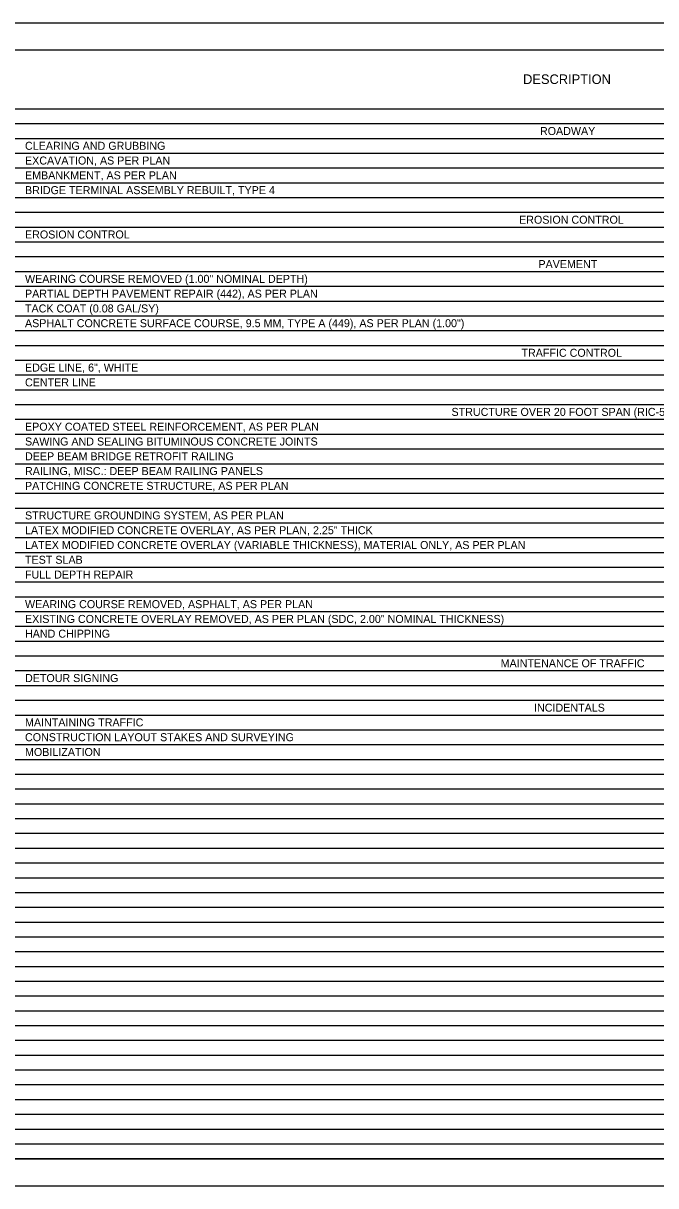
# Model space of a CAD drawing. Extents: x 0 to 34, y 0 to 22.
# Drawn here: x 10.49 to 22.45, y 0 to 22 of the extents above; entities that cross this region are included whole.
import ezdxf

# ---------------------------------------------------------------- set-up
doc = ezdxf.new("R2010")
doc.units = 0
for name, color, linetype in [('SH_Border', 7, 'Continuous'), ('SH_Cut_Line', 7, 'Continuous'), ('SH_Text', 7, 'Continuous')]:
    doc.layers.add(name, color=color, linetype=linetype)

msp = doc.modelspace()

# ---------------------------------------------------------------- linework, layer by layer
at = {"layer": 'SH_Border'}
msp.add_lwpolyline([(1.5, 21.5), (33.5, 21.5), (33.5, 0.5), (1.5, 0.5)], close=True, dxfattribs=at)
at = {"layer": 'SH_Cut_Line'}
msp.add_lwpolyline([(0, 0), (34, 0), (34, 22), (0, 22)], close=True, dxfattribs=at)
at = {"layer": 'SH_Text'}
for p, q in [((1.5, 21.5), (32, 21.5)), ((1.5, 20.381), (32, 20.381)), ((1.5, 20.101), (32, 20.101)), ((1.5, 19.821), (32, 19.821)), ((1.5, 19.541), (32, 19.541)), ((1.5, 19.261), (32, 19.261)), ((1.5, 18.982), (32, 18.982)), ((1.5, 18.702), (32, 18.702)), ((1.5, 18.422), (32, 18.422)), ((1.5, 18.142), (32, 18.142)), ((1.5, 17.862), (32, 17.862)), ((1.5, 17.583), (32, 17.583)), ((1.5, 17.303), (32, 17.303)), ((1.5, 17.023), (32, 17.023)), ((1.5, 16.743), (32, 16.743)), ((1.5, 16.463), (32, 16.463)), ((1.5, 16.183), (32, 16.183)), ((1.5, 15.904), (32, 15.904)), ((1.5, 15.624), (32, 15.624)), ((1.5, 15.344), (32, 15.344)), ((1.5, 15.064), (32, 15.064)), ((1.5, 14.784), (32, 14.784)), ((1.5, 14.505), (32, 14.505)), ((1.5, 14.225), (32, 14.225)), ((1.5, 13.945), (32, 13.945)), ((1.5, 13.665), (32, 13.665)), ((1.5, 13.385), (32, 13.385)), ((1.5, 13.106), (32, 13.106)), ((1.5, 12.826), (32, 12.826)), ((1.5, 12.546), (32, 12.546)), ((1.5, 12.266), (32, 12.266)), ((1.5, 11.986), (32, 11.986)), ((1.5, 11.706), (32, 11.706)), ((1.5, 11.427), (32, 11.427)), ((1.5, 11.147), (32, 11.147)), ((1.5, 10.867), (32, 10.867)), ((1.5, 10.587), (32, 10.587)), ((1.5, 10.307), (32, 10.307)), ((1.5, 10.028), (32, 10.028)), ((1.5, 9.748), (32, 9.748)), ((1.5, 9.468), (32, 9.468)), ((1.5, 9.188), (32, 9.188)), ((1.5, 8.908), (32, 8.908)), ((1.5, 8.628), (32, 8.628)), ((1.5, 8.349), (32, 8.349)), ((1.5, 8.069), (32, 8.069)), ((1.5, 7.789), (32, 7.789)), ((1.5, 7.509), (32, 7.509)), ((1.5, 7.229), (32, 7.229)), ((1.5, 6.95), (32, 6.95)), ((1.5, 6.67), (32, 6.67)), ((1.5, 6.39), (32, 6.39)), ((1.5, 6.11), (32, 6.11)), ((1.5, 5.83), (32, 5.83)), ((1.5, 5.55), (32, 5.55)), ((1.5, 5.271), (32, 5.271)), ((1.5, 4.991), (32, 4.991)), ((1.5, 4.711), (32, 4.711)), ((1.5, 4.431), (32, 4.431)), ((1.5, 4.151), (32, 4.151)), ((1.5, 3.872), (32, 3.872)), ((1.5, 3.592), (32, 3.592)), ((1.5, 3.312), (32, 3.312)), ((1.5, 3.032), (32, 3.032)), ((1.5, 2.752), (32, 2.752)), ((1.5, 2.472), (32, 2.472)), ((1.5, 2.193), (32, 2.193)), ((1.5, 1.913), (32, 1.913)), ((1.5, 1.633), (32, 1.633)), ((1.5, 1.353), (32, 1.353)), ((1.5, 1.073), (32, 1.073)), ((1.5, 0.794), (32, 0.794)), ((1.5, 0.514), (32, 0.514))]:
    msp.add_line(p, q, dxfattribs=at)

# ---------------------------------------------------------------- texts
for s, height, p in [('DESCRIPTION', 0.18172, (19.94, 20.85)), ('ROADWAY', 0.1514, (20.259, 19.885)), ('CLEARING AND GRUBBING', 0.15143, (10.52, 19.605)), ('EXCAVATION, AS PER PLAN', 0.15143, (10.52, 19.326)), ('EMBANKMENT, AS PER PLAN', 0.15143, (10.52, 19.046)), ('BRIDGE TERMINAL ASSEMBLY REBUILT, TYPE 4', 0.15143, (10.52, 18.766)), ('EROSION CONTROL', 0.15143, (19.864, 18.206)), ('EROSION CONTROL', 0.15143, (10.52, 17.927)), ('PAVEMENT', 0.1514, (20.23, 17.367)), ('WEARING COURSE REMOVED (1.00" NOMINAL DEPTH)', 0.15143, (10.52, 17.087)), ('PARTIAL DEPTH PAVEMENT REPAIR (442), AS PER PLAN', 0.15143, (10.52, 16.807)), ('TACK COAT (0.08 GAL/SY)', 0.15143, (10.52, 16.527)), ('ASPHALT CONCRETE SURFACE COURSE, 9.5 MM, TYPE A (449), AS PER PLAN (1.00")', 0.15143, (10.52, 16.248)), ('TRAFFIC CONTROL', 0.15143, (19.909, 15.688)), ('EDGE LINE, 6", WHITE', 0.15143, (10.52, 15.408)), ('CENTER LINE', 0.15143, (10.52, 15.128)), ('STRUCTURE OVER 20 FOOT SPAN (RIC-546-0498)', 0.15143, (18.586, 14.569)), ('EPOXY COATED STEEL REINFORCEMENT, AS PER PLAN', 0.15143, (10.52, 14.289)), ('SAWING AND SEALING BITUMINOUS CONCRETE JOINTS', 0.15143, (10.52, 14.009)), ('DEEP BEAM BRIDGE RETROFIT RAILING', 0.15143, (10.52, 13.729)), ('RAILING, MISC.: DEEP BEAM RAILING PANELS', 0.15143, (10.52, 13.45)), ('PATCHING CONCRETE STRUCTURE, AS PER PLAN', 0.15143, (10.52, 13.17)), ('STRUCTURE GROUNDING SYSTEM, AS PER PLAN', 0.15143, (10.52, 12.61)), ('LATEX MODIFIED CONCRETE OVERLAY, AS PER PLAN, 2.25" THICK', 0.15143, (10.52, 12.33)), ('LATEX MODIFIED CONCRETE OVERLAY (VARIABLE THICKNESS), MATERIAL ONLY, AS PER PLAN', 0.15143, (10.52, 12.05)), ('TEST SLAB', 0.1514, (10.52, 11.771)), ('FULL DEPTH REPAIR', 0.15143, (10.52, 11.491)), ('WEARING COURSE REMOVED, ASPHALT, AS PER PLAN', 0.15143, (10.52, 10.931)), ('EXISTING CONCRETE OVERLAY REMOVED, AS PER PLAN (SDC, 2.00" NOMINAL THICKNESS)', 0.15143, (10.52, 10.651)), ('HAND CHIPPING', 0.15143, (10.52, 10.372)), ('MAINTENANCE OF TRAFFIC', 0.15143, (19.515, 9.812)), ('DETOUR SIGNING', 0.15143, (10.52, 9.532)), ('INCIDENTALS', 0.15143, (20.147, 8.972)), ('MAINTAINING TRAFFIC', 0.15143, (10.52, 8.693)), ('CONSTRUCTION LAYOUT STAKES AND SURVEYING', 0.15143, (10.52, 8.413)), ('MOBILIZATION', 0.15143, (10.52, 8.133))]:
    msp.add_text(s, height=height, dxfattribs=at).set_placement(p)

doc.saveas('drawing.dxf')
